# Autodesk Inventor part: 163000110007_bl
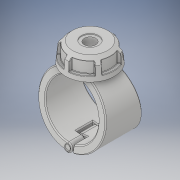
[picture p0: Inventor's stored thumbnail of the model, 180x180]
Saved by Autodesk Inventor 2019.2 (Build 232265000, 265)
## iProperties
Created: 2022-02
Part Number: 163000110007_bl
Material: Generic
Description: Plassadle Threaded 110x3/4''
Document SubType Name: Modeling
Designer: comp2
Density: 1 g/cm^3
Appearance: Default
Author: comp2
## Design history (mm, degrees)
derived "16300.ipt"
feature "Solid1::16300.ipt" dims "ScaleForDerivedMember" = 10
feature "Solid2::16300.ipt" dims "ScaleForDerivedMember" = 10
feature "Solid3::16300.ipt" dims "ScaleForDerivedMember" = 10
feature "Solid4::16300.ipt" dims "ScaleForDerivedMember" = 10
tag "TaggingFeature1"
body "Solid1"
body "Solid2"
body "Solid3"
body "Solid4"
other parameters: "d2" = 141 [user parameter], "d3" = 55 [user parameter], "d7" = 133.95 [user parameter], "d8" = 85 deg [user parameter], "d9" = 45 deg [user parameter], "d10" = 102 [user parameter], "d11" = 49 [user parameter], "d12" = 27.7935 [user parameter], "d13" = 42.84 [user parameter], "d14" = 36.1755 [user parameter], "d42" = 3.1 [user parameter], "d49" = 2.82 [user parameter], "d50" = 97 [user parameter], "d51" = 0 [user parameter], "d52" = 21.7 [user parameter], "d53" = 77.55 [user parameter], "d54" = 33.95 [user parameter], "d55" = 0 [user parameter], "d56" = 19.4 [user parameter], "d57" = 19.4 [user parameter], "d59" = 0 [user parameter], "d60" = 97 [user parameter], "d61" = 0 [user parameter], "d62" = 33.95 [user parameter], "d63" = 0 [user parameter], "d65" = 0 [user parameter], "d67" = 0 [user parameter], "d69" = 0 [user parameter], "d70" = 1 [user parameter], "d71" = 93.12 [user parameter], "d72" = 0 [user parameter], "d73" = 2 [user parameter], "d78" = 86.7 [user parameter], "d79" = 5.1 [user parameter], "d80" = 60 deg [user parameter], "d81" = 5.1 [user parameter], "d84" = 0 [user parameter], "d85" = 1 [user parameter], "d87" = 360 deg [user parameter], "d122" = 49 [user parameter], "d124" = 42.80128 [user parameter], "d125" = 1.98525 [user parameter], "d129" = 24.117 [user parameter], "d130" = 20.49945 [user parameter], "d131" = 31.85 [user parameter], "d132" = 45 deg [user parameter], "d133" = 22.295 [user parameter], "d134" = 12.0585 [user parameter], "d136" = 0 [user parameter], "d138" = 0 [user parameter], "d1" = 25 [user parameter], "B" = 141 [user parameter], "L" = 97 [user parameter], "E_" = 54 [user parameter], "E1" = 102 [user parameter], "H2" = 49 [user parameter], "H3" = 78 [user parameter], "H_costum" = 49 [user parameter], "Rp" = 24.117 [user parameter], "d128" = 39.705 [user parameter]
